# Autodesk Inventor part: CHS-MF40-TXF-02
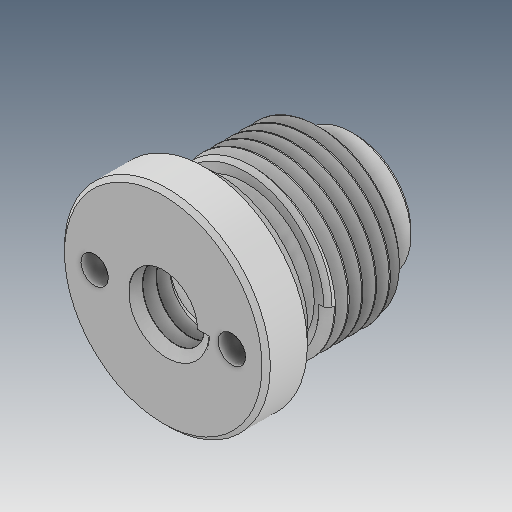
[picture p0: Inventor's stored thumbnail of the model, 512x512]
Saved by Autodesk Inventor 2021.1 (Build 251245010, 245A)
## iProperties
Created: 2019-05
Part Number: CHS-MF40-TXF-02
Material: Ogólny
Document SubType Name: Modeling
Designer: user
Density: 1 g/cm^3
Appearance: Domyślna
Author: user
Revision Number: ÈÎºÎ
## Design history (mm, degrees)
feature "ÊäÈë1"
node "Bryła1"
